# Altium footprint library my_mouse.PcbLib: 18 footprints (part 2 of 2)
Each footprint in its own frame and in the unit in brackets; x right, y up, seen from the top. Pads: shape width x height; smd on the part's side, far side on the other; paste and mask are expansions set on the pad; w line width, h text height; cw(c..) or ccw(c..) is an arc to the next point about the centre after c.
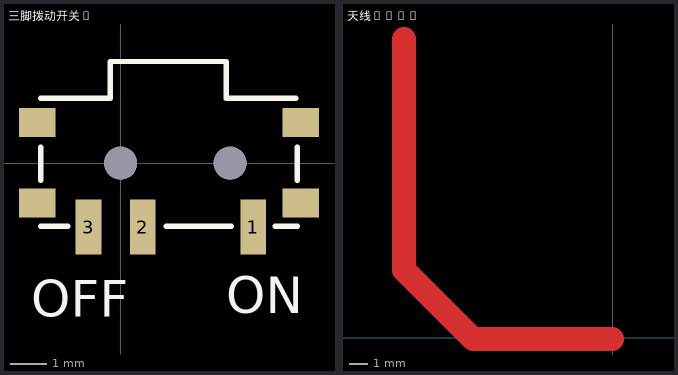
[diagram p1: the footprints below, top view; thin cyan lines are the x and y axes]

## 三脚拨动开关2 [mm]
pads (9):
  rect 0.7x1.5 smd: 1(3.62,-1.745) 2(0.6,-1.745) 3(-0.88,-1.745)
  rect 1x0.8 smd: ""(-2.28,-1.09) ""(-2.28,1.11) ""(4.92,-1.09) ""(4.92,1.11)
  round 0.9 hole 0.9: ""(0,0) ""(2.99,0)
Top Overlay:
  lines w0.15: -2.18,-1.72 -1.45,-1.72 ; -2.18,-0.47 -2.18,0.43 ; -2.18,1.78 -0.28,1.78 -0.28,2.78 2.88,2.78 2.88,1.78 4.78,1.78 ; 1.24,-1.72 3.02,-1.72 ; 4.22,-1.72 4.82,-1.72 ; 4.82,-0.47 4.82,0.43
  text "ON" at 2.89,-4.1 h1
  text "OFF" at -2.45,-4.19 h1

## 天线_PCB [mm]
Top Layer:
  lines w1.27: -11.122,15.906 -11.122,3.612 -7.439,-0.071 -0.048,-0.071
